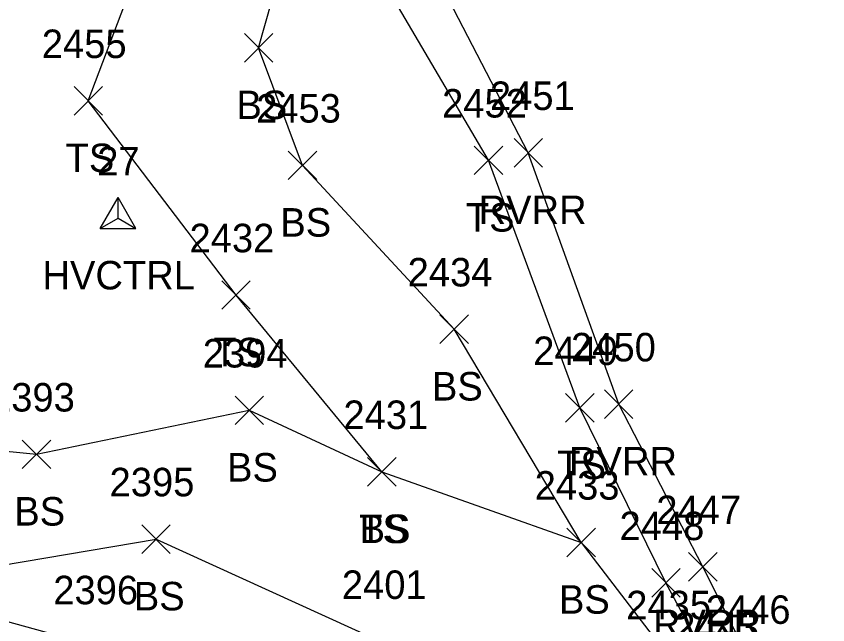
# Model space of a CAD drawing. Extents: x 1461855 to 1464118, y 556196 to 557441.
# Drawn here: x 1462099 to 1462156, y 556461.7 to 556504.3 of the extents above; entities that cross this region are included whole.
import ezdxf

# ---------------------------------------------------------------- set-up
doc = ezdxf.new("R2010")
doc.units = 0
for name, color, linetype in [('C_A', 7, 'Continuous'), ('C_I', 7, 'Continuous'), ('CPSM', 7, 'Continuous'), ('L_A', 7, 'Continuous'), ('L_I', 7, 'Continuous'), ('L_TIC', 7, 'Continuous'), ('LAWE', 7, 'Continuous'), ('LELB', 7, 'Continuous'), ('R_I', 7, 'Continuous'), ('S_I', 7, 'Continuous')]:
    doc.layers.add(name, color=color, linetype=linetype)

msp = doc.modelspace()

# ---------------------------------------------------------------- linework, layer by layer
at = {"layer": 'CPSM'}
for p, q in [((1462104.927, 556489.464), (1462106.177, 556491.629)), ((1462107.427, 556489.464), (1462106.177, 556491.629)), ((1462106.177, 556490.185), (1462106.177, 556491.629)), ((1462104.927, 556489.464), (1462106.177, 556490.185)), ((1462106.177, 556490.185), (1462106.177, 556490.185)), ((1462106.177, 556490.185), (1462107.427, 556489.464)), ((1462104.927, 556489.464), (1462107.427, 556489.464))]:
    msp.add_line(p, q, dxfattribs=at)
at = {"layer": 'L_TIC'}
for points in [[(1462115.038, 556501.128), (1462117.038, 556503.128)], [(1462117.038, 556501.128), (1462115.038, 556503.128)], [(1462103.084, 556497.411), (1462105.084, 556499.411)], [(1462105.084, 556497.411), (1462103.084, 556499.411)], [(1462133.96, 556493.769), (1462135.96, 556495.769)], [(1462135.96, 556493.769), (1462133.96, 556495.769)], [(1462131.17, 556493.241), (1462133.17, 556495.241)], [(1462133.17, 556493.241), (1462131.17, 556495.241)], [(1462118.119, 556492.887), (1462120.119, 556494.887)], [(1462120.119, 556492.887), (1462118.119, 556494.887)], [(1462113.451, 556483.791), (1462115.451, 556485.791)], [(1462115.451, 556483.791), (1462113.451, 556485.791)], [(1462128.754, 556481.393), (1462130.754, 556483.393)], [(1462130.754, 556481.393), (1462128.754, 556483.393)], [(1462140.304, 556476.136), (1462142.304, 556478.136)], [(1462142.304, 556476.136), (1462140.304, 556478.136)], [(1462114.381, 556475.71), (1462116.381, 556477.71)], [(1462116.381, 556475.71), (1462114.381, 556477.71)], [(1462137.573, 556475.881), (1462139.573, 556477.881)], [(1462139.573, 556475.881), (1462137.573, 556477.881)], [(1462099.452, 556472.623), (1462101.452, 556474.623)], [(1462101.452, 556472.623), (1462099.452, 556474.623)], [(1462123.684, 556471.395), (1462125.684, 556473.395)], [(1462125.684, 556471.395), (1462123.684, 556473.395)], [(1462123.684, 556471.395), (1462125.684, 556473.395)], [(1462125.684, 556471.395), (1462123.684, 556473.395)], [(1462107.839, 556466.675), (1462109.839, 556468.675)], [(1462109.839, 556466.675), (1462107.839, 556468.675)], [(1462137.668, 556466.443), (1462139.668, 556468.443)], [(1462139.668, 556466.443), (1462137.668, 556468.443)], [(1462137.668, 556466.443), (1462139.668, 556468.443)], [(1462139.668, 556466.443), (1462137.668, 556468.443)], [(1462146.201, 556464.728), (1462148.201, 556466.728)], [(1462148.201, 556464.728), (1462146.201, 556466.728)], [(1462143.619, 556463.603), (1462145.619, 556465.603)], [(1462145.619, 556463.603), (1462143.619, 556465.603)]]:
    msp.add_lwpolyline(points, dxfattribs=at)
at = {"layer": 'LAWE'}
msp.add_lwpolyline([(1462154.863, 556328.185), (1462154.036, 556339.342), (1462154.572, 556350.205), (1462152.486, 556361.373), (1462151.238, 556373.266), (1462149.161, 556381.463), (1462150.123, 556395.584), (1462150.659, 556404.988), (1462152.286, 556411.553), (1462152.849, 556416.044), (1462153.935, 556421.507), (1462155.971, 556453.801), (1462150.724, 556458.73), (1462147.201, 556465.728), (1462141.304, 556477.136), (1462134.96, 556494.769), (1462123.898, 556516.113), (1462120.543, 556522.084)], dxfattribs=at)
at = {"layer": 'LELB'}
for points in [[(1461963.705, 556606.006), (1461972.105, 556589.426), (1461974.569, 556579.664), (1461977.523, 556575.662), (1461983.683, 556561.117), (1461995.205, 556544.635), (1462001.849, 556531.766), (1462015.715, 556512.95), (1462031.601, 556494.072), (1462048.722, 556482.954), (1462068.844, 556473.098), (1462085.604, 556465.871), (1462095.004, 556462.84), (1462104.945, 556460.104), (1462122.08, 556455.999), (1462130.643, 556454.493), (1462134.696, 556456.084), (1462145.09, 556459.049)], [(1462138.668, 556467.443), (1462129.754, 556482.393), (1462119.119, 556493.887), (1462116.038, 556502.128), (1462119.768, 556515.328), (1462114.944, 556522.402), (1462101.003, 556522.593), (1462095.906, 556539.17), (1462080.848, 556539.724), (1462051.281, 556532.183), (1462037.062, 556530.069)], [(1462003.925, 556533.351), (1462018.122, 556515.464), (1462033.248, 556497.405), (1462071.175, 556477.093), (1462086.801, 556469.546), (1462096.393, 556465.563), (1462108.839, 556467.675), (1462124.65, 556460.477), (1462134.696, 556456.084)], [(1462124.684, 556472.395), (1462114.451, 556484.791), (1462104.084, 556498.411), (1462111.543, 556518.091)], [(1462151.76, 556453.627), (1462148.455, 556457.534), (1462144.619, 556464.603), (1462138.573, 556476.881), (1462132.17, 556494.241), (1462119.768, 556515.328)], [(1462073.826, 556488.172), (1462090.308, 556474.634), (1462100.452, 556473.623), (1462115.381, 556476.71), (1462124.684, 556472.395), (1462138.668, 556467.443), (1462145.09, 556459.049), (1462141.891, 556453.801), (1462147.501, 556452.882), (1462151.338, 556453.207)]]:
    msp.add_lwpolyline(points, dxfattribs=at)

# ---------------------------------------------------------------- texts
at = {"layer": 'C_A'}
msp.add_text('HVCTRL', height=2, dxfattribs=at).set_placement((1462100.87, 556485.185))
at = {"layer": 'C_I'}
msp.add_text('27', height=2, dxfattribs=at).set_placement((1462104.713, 556493.185))
at = {"layer": 'L_A'}
for s, p in [('BS', (1462114.479, 556497.128)), ('TS', (1462102.493, 556493.411)), ('RVRR', (1462131.472, 556489.769)), ('TS', (1462130.579, 556489.241)), ('BS', (1462117.56, 556488.887)), ('TS', (1462112.861, 556479.791)), ('BS', (1462128.195, 556477.393)), ('RVRR', (1462137.816, 556472.136)), ('BS', (1462113.822, 556471.71)), ('TS', (1462136.982, 556471.881)), ('BS', (1462098.893, 556468.623)), ('TS', (1462123.094, 556467.395)), ('BS', (1462123.125, 556467.395)), ('BS', (1462107.28, 556462.675)), ('BS', (1462137.109, 556462.443)), ('BS', (1462137.109, 556462.443)), ('RVRR', (1462143.712, 556460.728))]:
    msp.add_text(s, height=2, dxfattribs=at).set_placement(p)
at = {"layer": 'L_I'}
for s, p in [('2455', (1462100.824, 556501.411)), ('2451', (1462132.267, 556497.769)), ('2452', (1462128.91, 556497.241)), ('2453', (1462115.859, 556496.887)), ('2432', (1462111.191, 556487.791)), ('2434', (1462126.495, 556485.393)), ('2450', (1462137.958, 556480.136)), ('2394', (1462112.121, 556479.71)), ('2449', (1462135.305, 556479.881)), ('2393', (1462097.192, 556476.623)), ('2431', (1462121.991, 556475.395)), ('2431', (1462121.991, 556475.395)), ('2395', (1462105.579, 556470.675)), ('2433', (1462135.408, 556470.443)), ('2433', (1462135.408, 556470.443)), ('2447', (1462143.941, 556468.728)), ('2448', (1462141.359, 556467.603)), ('2396', (1462101.63, 556463.104)), ('2401', (1462121.879, 556463.477)), ('2435', (1462141.83, 556462.049)), ('2435', (1462141.83, 556462.049)), ('2446', (1462147.409, 556461.73)), ('2443', (1462145.195, 556460.534))]:
    msp.add_text(s, height=2, dxfattribs=at).set_placement(p)
at = {"layer": 'R_I'}
msp.add_text('2396', height=2, dxfattribs=at).set_placement((1462101.63, 556463.104))
at = {"layer": 'S_I'}
msp.add_text('2443', height=2, dxfattribs=at).set_placement((1462145.195, 556460.534))

doc.saveas('drawing.dxf')
